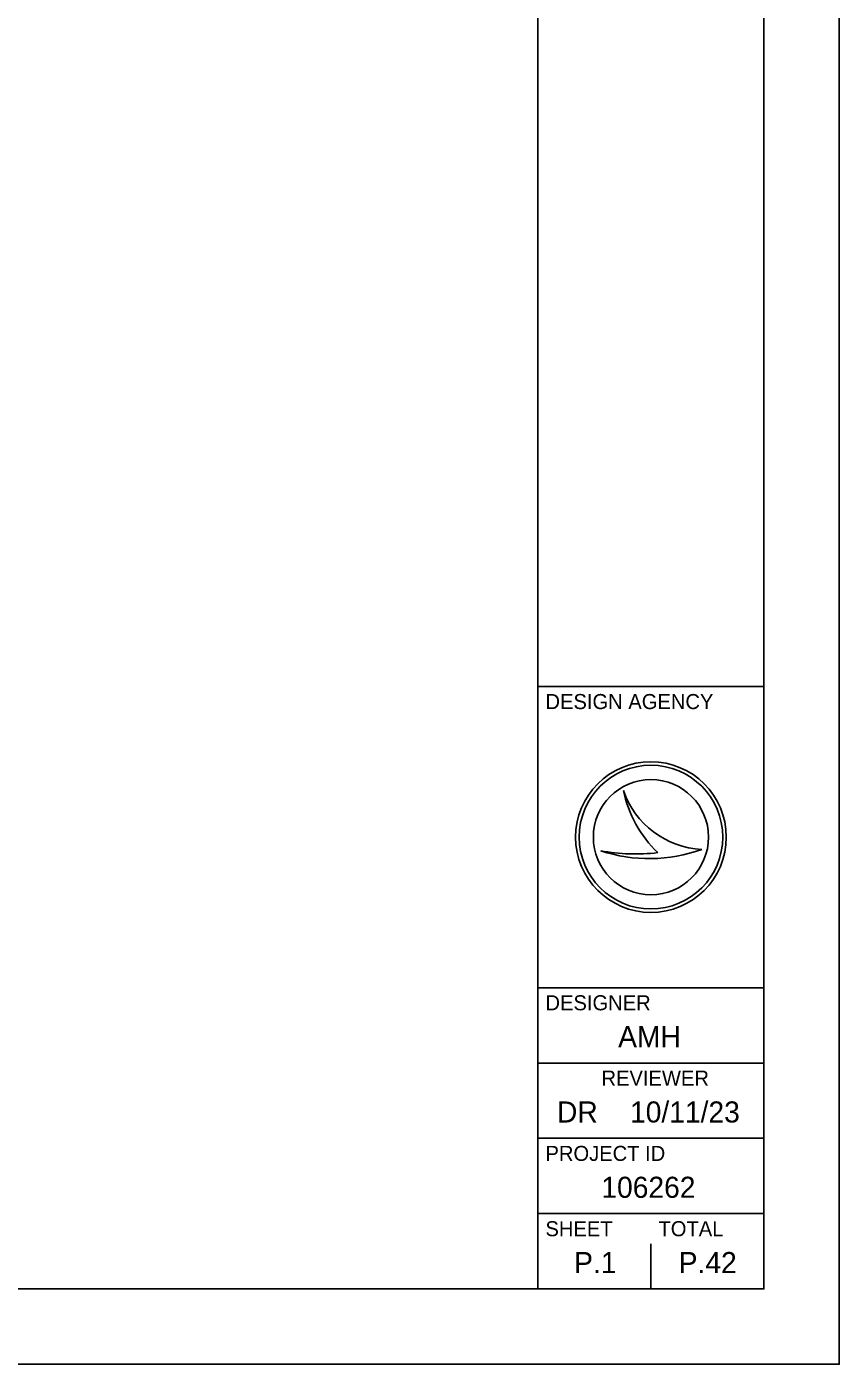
# Model space of a CAD drawing. Extents: x 0 to 34, y 0 to 22.
# Drawn here: x 28.61 to 34, y 0 to 8.88 of the extents above; entities that cross this region are included whole.
import ezdxf

# ---------------------------------------------------------------- set-up
doc = ezdxf.new("R2010")
doc.units = 0
for name, color, linetype in [('SH_Border', 7, 'Continuous'), ('SH_Cut_Line', 7, 'Continuous'), ('SH_Data', 7, 'Continuous')]:
    doc.layers.add(name, color=color, linetype=linetype)

msp = doc.modelspace()

# ---------------------------------------------------------------- linework, layer by layer
at = {"layer": 'SH_Border'}
for p, q in [((32, 0.5), (32, 21.5)), ((32, 4.5), (33.5, 4.5)), ((32, 2.5), (33.5, 2.5)), ((32, 2), (33.5, 2)), ((32, 1.5), (33.5, 1.5)), ((32, 1), (33.5, 1))]:
    msp.add_line(p, q, dxfattribs=at)
msp.add_lwpolyline([(1.5, 21.5), (33.5, 21.5), (33.5, 0.5), (1.5, 0.5)], close=True, dxfattribs=at)
at = {"layer": 'SH_Cut_Line'}
msp.add_lwpolyline([(0, 0), (34, 0), (34, 22), (0, 22)], close=True, dxfattribs=at)
at = {"layer": 'SH_Data'}
for p, q in [((32.5674, 3.8096), (32.5675, 3.8096)), ((32.75, 3.5), (32.75, 3.5)), ((32.4172, 3.4095), (32.4172, 3.4095)), ((33.0873, 3.4185), (33.0873, 3.4185)), ((32.75, 0.5), (32.75, 0.8)), ((32.375, 0.675), (32.375, 0.675))]:
    msp.add_line(p, q, dxfattribs=at)
for radius in [0.5, 0.4768, 0.4768, 0.3822]:
    msp.add_circle((32.75, 3.5), radius, dxfattribs=at)
for centre, radius, start, end in [((33.1159, 3.9976), 0.5798, 198.92567, 198.93195), ((33.3467, 3.9701), 0.7956, 191.63793, 191.64215), ((33.1159, 3.9976), 0.5798, 198.93195, 267.16574), ((33.3467, 3.9701), 0.7956, 191.64215, 226.09467), ((32.7394, 4.37), 1.0131, 251.45764, 290.08324), ((32.648, 4.6543), 1.2661, 259.49639, 259.49952), ((32.7394, 4.37), 1.0131, 251.45274, 251.45764), ((32.648, 4.6543), 1.2661, 259.49952, 276.66723)]:
    msp.add_arc(centre, radius, start, end, dxfattribs=at)

# ---------------------------------------------------------------- texts
for s, height, p in [('DESIGN AGENCY', 0.1, (32.05, 4.35)), ('DESIGNER', 0.1, (32.05, 2.35)), ('AMH', 0.14, (32.5324, 2.105)), ('REVIEWER', 0.1, (32.4218, 1.85)), ('DR', 0.14, (32.1264, 1.605)), ('10/11/23', 0.14, (32.6113, 1.605)), ('PROJECT ID', 0.1, (32.05, 1.35)), ('106262', 0.14, (32.4209, 1.105)), ('SHEET', 0.1, (32.05, 0.85)), ('TOTAL', 0.1, (32.8, 0.85)), ('P.1', 0.14, (32.2403, 0.605)), ('P.42', 0.14, (32.9345, 0.605))]:
    msp.add_text(s, height=height, dxfattribs=at).set_placement(p)

doc.saveas('drawing.dxf')
